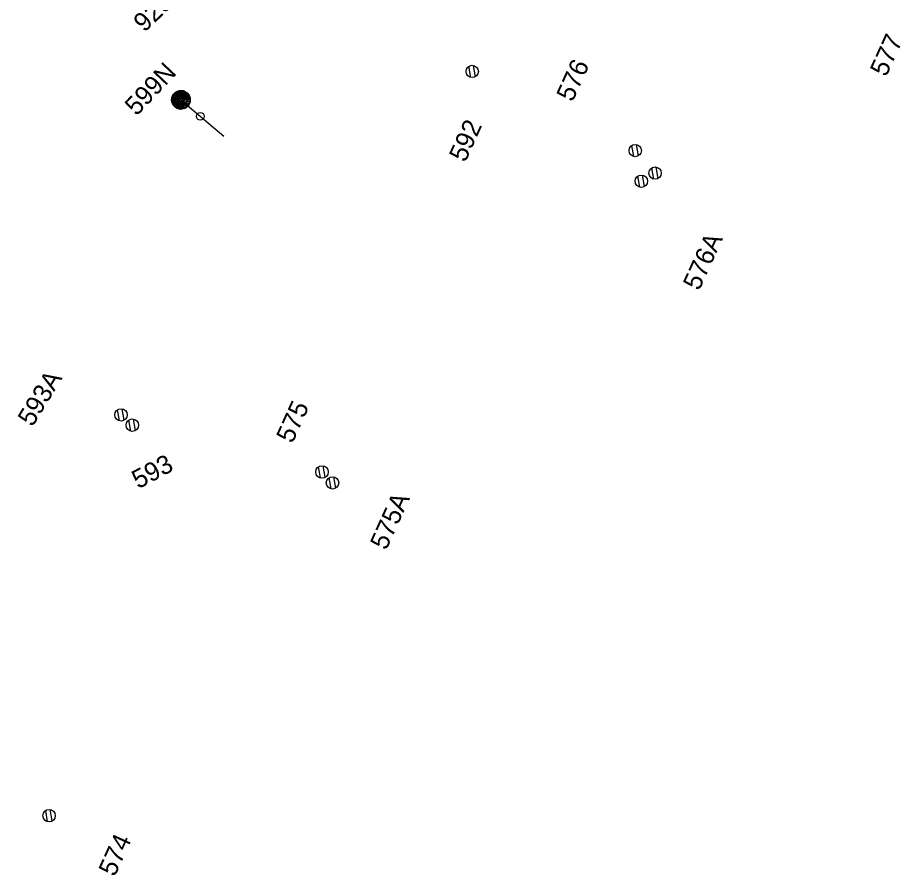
# Model space of a CAD drawing. Extents: x -595867 to -593796, y -1159595 to -1157495.
# Drawn here: x -594610.9 to -594539.7, y -1157845.8 to -1157776.6 of the extents above; entities that cross this region are included whole.
import ezdxf

# ---------------------------------------------------------------- set-up
doc = ezdxf.new("R2010")
doc.units = 0
for name, color, linetype in [('BVK_kanalizace_destova_nova', 7, 'Continuous'), ('BVK_kanalizace_jednotna_nova', 7, 'Continuous'), ('Teplarny Horkovod', 7, 'Continuous')]:
    doc.layers.add(name, color=color, linetype=linetype)

# ---------------------------------------------------------------- blocks, each defined once
blk = doc.blocks.new('st_tecka')
blk.add_circle((0, 0), 0.00314)
blk = doc.blocks.new('st_1t')
for points in [[(-0.00729, 0.00159), (0.00185, 0.00722), (0.00284, 0.0069), (-0.00742, 0.00071)], [(-0.00711, 0.00221), (0.00057, 0.00744), (0.00185, 0.00722), (-0.00729, 0.00159)], [(-0.00689, 0.00294), (-0.00011, 0.00749), (0.00057, 0.00744), (-0.00711, 0.00221)], [(-0.00669, 0.00331), (-0.00149, 0.00733), (-0.00011, 0.00749), (-0.00689, 0.00294)], [(-0.00627, 0.00403), (-0.00222, 0.00714), (-0.00149, 0.00733), (-0.00669, 0.00331)], [(-0.00579, 0.00472), (-0.00315, 0.00675), (-0.00222, 0.00714), (-0.00627, 0.00403)], [(-0.00742, 0.00071), (0.00284, 0.0069), (0.00359, 0.00656), (-0.00747, -0.00023)], [(-0.00747, -0.00023), (0.00359, 0.00656), (0.00442, 0.00605), (-0.00743, -0.00101)], [(-0.00743, -0.00101), (0.00442, 0.00605), (0.00522, 0.0054), (-0.00722, -0.0019)], [(-0.00722, -0.0019), (0.00522, 0.0054), (0.00588, 0.00461), (-0.00688, -0.00302)], [(-0.00688, -0.00302), (0.00588, 0.00461), (0.00666, 0.00341), (-0.00639, -0.00386)], [(-0.00639, -0.00386), (0.00666, 0.00341), (0.00712, 0.00224), (-0.00567, -0.00488)], [(-0.00526, 0.00533), (-0.00413, 0.00624), (-0.00315, 0.00675), (-0.00579, 0.00472)], [(-0.00567, -0.00488), (0.00712, 0.00224), (0.00742, 0.00112), (-0.00488, -0.00564)], [(-0.00488, -0.00564), (0.00742, 0.00112), (0.00748, -0.00042), (-0.00405, -0.00629)], [(-0.00405, -0.00629), (0.00748, -0.00042), (0.00729, -0.00175), (-0.00317, -0.00679)], [(-0.00317, -0.00679), (0.00729, -0.00175), (0.00698, -0.00275), (-0.00206, -0.00718)], [(-0.00206, -0.00718), (0.00698, -0.00275), (0.00651, -0.0037), (-0.00114, -0.0074)], [(-0.00114, -0.0074), (0.00651, -0.0037), (0.00592, -0.00458), (-0.00048, -0.00747)], [(-0.00048, -0.00747), (0.00592, -0.00458), (0.00536, -0.00524), (0.00037, -0.00747)], [(0.00037, -0.00747), (0.00536, -0.00524), (0.00449, -0.00597), (0.00138, -0.00739)], [(0.00138, -0.00739), (0.00449, -0.00597), (0.00384, -0.00644), (0.0025, -0.00702)], [(0.0025, -0.00702), (0.00384, -0.00644), (0.00295, -0.00692), (0.00293, -0.00693)]]:
    blk.add_lwpolyline(points, close=True)
blk.add_circle((0, 0), 0.0075)
blk = doc.blocks.new('st1k_1t')
blk.add_line((0, 0), (0.04531, 0))
blk.add_blockref('st_1t', (0, 0))
at = {"rotation": 90}
blk.add_blockref('st_tecka', (0.02054, 0), dxfattribs=at)

msp = doc.modelspace()

# ---------------------------------------------------------------- linework, layer by layer
at = {"layer": 'BVK_kanalizace_jednotna_nova'}
for p, q in [((-594574.003, -1157781.404), (-594574.165, -1157780.492)), ((-594574.373, -1157781.462), (-594574.533, -1157780.563)), ((-594597.831, -1157783.758), (-594598.032, -1157782.867)), ((-594597.464, -1157783.682), (-594597.667, -1157782.779)), ((-594560.863, -1157787.784), (-594561.025, -1157786.872)), ((-594561.233, -1157787.842), (-594561.393, -1157786.943)), ((-594559.633, -1157789.653), (-594559.793, -1157788.754)), ((-594559.263, -1157789.595), (-594559.425, -1157788.683)), ((-594560.743, -1157790.312), (-594560.903, -1157789.413)), ((-594560.373, -1157790.254), (-594560.535, -1157789.342)), ((-594602.683, -1157809.143), (-594602.843, -1157808.244)), ((-594602.313, -1157809.085), (-594602.475, -1157808.173)), ((-594601.772, -1157809.972), (-594601.932, -1157809.073)), ((-594601.402, -1157809.914), (-594601.564, -1157809.002)), ((-594586.483, -1157813.743), (-594586.643, -1157812.844)), ((-594586.113, -1157813.685), (-594586.275, -1157812.773)), ((-594585.633, -1157814.623), (-594585.793, -1157813.724)), ((-594585.263, -1157814.565), (-594585.425, -1157813.653)), ((-594608.483, -1157841.442), (-594608.643, -1157840.543)), ((-594608.113, -1157841.384), (-594608.275, -1157840.472))]:
    msp.add_line(p, q, dxfattribs=at)
for centre in [(-594574.26, -1157780.979), (-594574.26, -1157780.979), (-594597.74, -1157783.27), (-594597.74, -1157783.27), (-594561.12, -1157787.359), (-594561.12, -1157787.359), (-594559.52, -1157789.17), (-594559.52, -1157789.17), (-594560.63, -1157789.829), (-594560.63, -1157789.829), (-594602.57, -1157808.66), (-594602.57, -1157808.66), (-594601.659, -1157809.489), (-594601.659, -1157809.489), (-594586.37, -1157813.26), (-594586.37, -1157813.26), (-594585.52, -1157814.14), (-594585.52, -1157814.14), (-594608.37, -1157840.959), (-594608.37, -1157840.959)]:
    msp.add_circle(centre, 0.5, dxfattribs=at)

# ---------------------------------------------------------------- block references
at = {"layer": 'BVK_kanalizace_destova_nova', "xscale": 99.99999999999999, "yscale": 100, "rotation": -40.17904596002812}
msp.add_blockref('st1k_1t', (-594597.74, -1157783.27), dxfattribs=at)

# ---------------------------------------------------------------- texts
at = {"layer": 'BVK_kanalizace_destova_nova'}
msp.add_text('599N', height=1.5, rotation=46.56899, dxfattribs=at).set_placement((-594601.316, -1157784.626))
at = {"layer": 'BVK_kanalizace_jednotna_nova'}
for s, rotation, p in [('577', 65.59844, (-594540.894, -1157781.476)), ('576', 65.59844, (-594566.173, -1157783.498)), ('592', 65.59844, (-594574.821, -1157788.365)), ('576A', 65.59844, (-594555.969, -1157798.707)), ('593A', 58.68454, (-594609.706, -1157809.678)), ('575', 65.59844, (-594588.756, -1157811.022)), ('593', 27.99692, (-594601.182, -1157814.656)), ('575A', 65.59844, (-594581.194, -1157819.625)), ('574', 65.59844, (-594603.078, -1157845.934))]:
    msp.add_text(s, height=1.5, rotation=rotation, dxfattribs=at).set_placement(p)
at = {"layer": 'Teplarny Horkovod'}
msp.add_text('928', height=1.5, rotation=43.54065, dxfattribs=at).set_placement((-594600.69, -1157777.876))

doc.saveas('drawing.dxf')
